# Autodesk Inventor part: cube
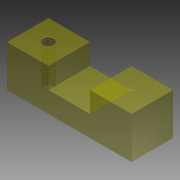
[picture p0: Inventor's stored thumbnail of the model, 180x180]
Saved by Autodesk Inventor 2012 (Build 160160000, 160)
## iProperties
Created: 2013-09
Part Number: cube
Material: Default
Document SubType Name: Modeling
Designer: hilarion
Density: 1 g/cm^3
Author: hilarion
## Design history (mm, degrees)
sketch "Esquisse1"
  geometry: L1 (0, 0)-(20, 0); L2 (20, 0)-(20, 20); L3 (20, 20)-(0, 20); L4 (0, 20)-(0, 0)
  constraints: 8 end point, 2 parallel, 1 horizontal, 1 perpendicular
  dimensions: "d0" = 20 distance of L3.end L2.end; "d1" = 20 distance of L2.end L1.end
extrude "Extrusion1" new body sketch "Esquisse1" distance "d2" = 20; taper "d3" = 0 deg
sketch "Esquisse2"
  geometry: 1 further point
hole "Perçage1" sketch "Esquisse2" at (10, 10) diameter "d4" = 4.917; stored, may be unused: countersink angle "d8" = 90 deg, drill point angle "d10" = 118 deg; dims "d5" = 6, "d6" = 4, "d7" = 2, "d9" = 8
sketch "Esquisse4"
  geometry: L1 (0, 0)-(-20, 0) reference; L2 (0, 20)-(-10, 20); L3 (-10, 20)-(-10, 0); L4 (-10, 0)-(0, 0); L5 (0, 0)-(0, 20)
  constraints: 8 end point, 2 parallel, 1 horizontal, 1 midpoint, 1 perpendicular
extrude "Extrusion2" join sketch "Esquisse4" distance "d18" = 20; taper "d19" = 0 deg
sketch "Esquisse5"
  geometry: L1 (0, 20)-(-20, 20); L2 (-20, 20)-(-20, 0); L3 (-20, 0)-(0, 0); L4 (0, 0)-(0, 20)
  constraints: 8 end point, 2 parallel, 1 horizontal, 1 perpendicular
  dimensions: "d20" = 20 distance of L3.end L2.end
extrude "Extrusion3" join sketch "Esquisse5" distance "d21" = 20; taper "d22" = 0 deg
node "Solide1"
sketch "Esquisse7"
  geometry: 1 further point
